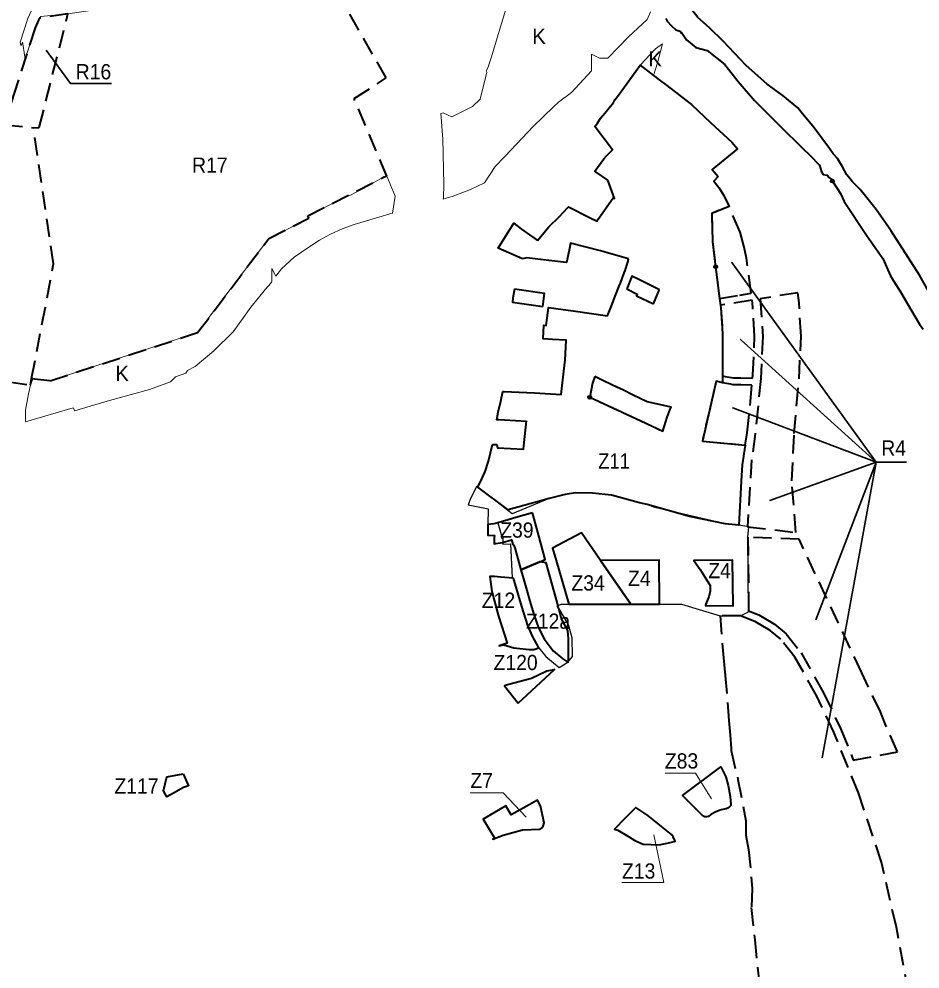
# Model space of a CAD drawing. Extents: x -650276 to -642489, y -1074311 to -1066658.
# Drawn here: x -646603 to -645184, y -1070690 to -1069193 of the extents above; entities that cross this region are included whole.
import ezdxf

# ---------------------------------------------------------------- set-up
doc = ezdxf.new("R2010")
doc.units = 0
doc.header["$LTSCALE"] = 9.6
doc.header["$PDMODE"] = 32
doc.header["$PDSIZE"] = 4.8
doc.linetypes.add('MEDIUM_DASHED', pattern=[4.5, 3, -1.5])
for name, color, linetype, lineweight in [('42', 7, 'Continuous', 25), ('44', 7, 'Continuous', 40), ('45', 7, 'Continuous', 40), ('46', 7, 'Continuous', 13), ('47', 7, 'Continuous', 13), ('48', 7, 'Continuous', 13), ('61', 7, 'MEDIUM_DASHED', 40), ('62', 7, 'Continuous', 35)]:
    doc.layers.add(name, color=color, linetype=linetype, lineweight=lineweight)

msp = doc.modelspace()

# ---------------------------------------------------------------- linework, layer by layer
at = {"layer": '42'}
msp.add_lwpolyline([(-645637.56, -1070114.89), (-645559.63, -1070114.85), (-645499.129, -1070133.293), (-645466.862, -1070133.219), (-645454.051, -1070127.008), (-645455.073, -1070009.111), (-645453.852, -1069992.968), (-645469.701, -1069990.011), (-645490.814, -1069988.074), (-645601.753, -1069962.317), (-645614.072, -1069957.797), (-645625.979, -1069954.92), (-645670.325, -1069943.002), (-645699.889, -1069939.714), (-645726.542, -1069939.398), (-645742.967, -1069941.862), (-645768.424, -1069948.431), (-645826.321, -1069972.247), (-645880.431, -1069930.3), (-645882.381, -1069928.788), (-645892.09, -1069947.98), (-645895.66, -1069958.42), (-645864.48, -1069964.53), (-645864.77, -1069989.26), (-645855.54, -1069988.24), (-645849.1, -1069986.42), (-645842.8, -1070008.59), (-645843.74, -1070010.25), (-645841.43, -1070010.21), (-645841.21, -1070017.31), (-645841.89, -1070017.42), (-645841.075, -1070020.163), (-645828.963, -1070019.709), (-645826.615, -1070073.495), (-645824.28, -1070073.67), (-645811.48, -1070118.65), (-645801.99, -1070148.51), (-645795.07, -1070164.26), (-645784.51, -1070183.77), (-645773.48, -1070197.1), (-645752.54, -1070214.74), (-645739.12, -1070205.9), (-645731.3, -1070197.24), (-645731.94, -1070167.87), (-645737.63, -1070147.39), (-645755.4, -1070117.6), (-645749.28, -1070114.96), (-645737.075, -1070114.955)], close=True, dxfattribs=at)
at = {"layer": '44'}
for points in [[(-645166.67, -1069629), (-645184.88, -1069596.58), (-645202.56, -1069568.23), (-645230.1, -1069525.98), (-645253.4, -1069493.06), (-645278.31, -1069461.33), (-645281.4, -1069458.4), (-645290.5, -1069449.03), (-645299.61, -1069437.97), (-645306.16, -1069425.55), (-645314.14, -1069412.54), (-645321.1, -1069405.21), (-645326.59, -1069396.64), (-645350.63, -1069363.98), (-645371.12, -1069339.47), (-645376.38, -1069332.65), (-645400.07, -1069313.32), (-645424.8, -1069295.24), (-645458.45, -1069265.56), (-645494.13, -1069227.63), (-645515.89, -1069206.66), (-645534.25, -1069190.56), (-645543.43, -1069178.39)], [(-645584.73, -1069191.88), (-645582.63, -1069195.88), (-645575.58, -1069203.57), (-645568.9, -1069209.87), (-645567.07, -1069210.45), (-645562.17, -1069212.02), (-645560.72, -1069214.25), (-645559.33, -1069214.54), (-645552.2, -1069225.59), (-645537.44, -1069237.41), (-645519.59, -1069242.38), (-645491.63, -1069264.25), (-645470.44, -1069291.24), (-645444.62, -1069321.35), (-645405.7, -1069360.27), (-645368.13, -1069397.37), (-645358.04, -1069406.84), (-645342.49, -1069423.06), (-645339.31, -1069433.27), (-645336.66, -1069437.47), (-645330.57, -1069438.89), (-645327.2, -1069442.53), (-645323.36, -1069445.79), (-645322.13, -1069447.96)], [(-645322.13, -1069447.96), (-645309.62, -1069467.79), (-645303.57, -1069480.49), (-645268.57, -1069533.23), (-645242.75, -1069570.26), (-645230.42, -1069597.39), (-645227.27, -1069602.68), (-645225.7, -1069605.32), (-645214.76, -1069622.37), (-645198.41, -1069650.49), (-645185.17, -1069673.38), (-645179.12, -1069681.3)]]:
    msp.add_lwpolyline(points, dxfattribs=at)
at = {"layer": '44', "lineweight": 13}
msp.add_lwpolyline([(-645585.63, -1070380.811), (-645537.799, -1070380.811), (-645512.608, -1070421.471)], dxfattribs=at)
msp.add_lwpolyline([(-645585.63, -1070380.811), (-645537.799, -1070380.811), (-645512.608, -1070421.471)], dxfattribs=at)
at = {"layer": '44'}
msp.add_lwpolyline([(-645497.81, -1070370.93), (-645497.81, -1070370.93), (-645490.19, -1070386.97), (-645486.54, -1070400.38), (-645483.29, -1070417.99), (-645482.62, -1070423.93), (-645481.93, -1070430.04), (-645482.18, -1070432.13), (-645485.67, -1070435.7), (-645489.34, -1070437.05), (-645497.33, -1070438.82), (-645505.88, -1070441.74), (-645513.81, -1070446.24), (-645517.44, -1070449.23), (-645517.95, -1070449.45), (-645520.4, -1070449.87), (-645521.41, -1070449.84), (-645522.95, -1070449.61), (-645524.42, -1070449.16), (-645525.75, -1070448.41), (-645527.34, -1070447.1), (-645558.36, -1070416.1)], close=True, dxfattribs=at)
msp.add_point((-645322.13, -1069447.96), dxfattribs=at)
at = {"layer": '45'}
for p, q in [((-645704.355, -1069788.786), (-645623.75, -1069825.97)), ((-645726.542, -1069939.398), (-645742.967, -1069941.862))]:
    msp.add_line(p, q, dxfattribs=at)
for points in [[(-645668.722, -1069398.75), (-645696.19, -1069362.01), (-645692.38, -1069356.67), (-645690.81, -1069354.28), (-645687.22, -1069349), (-645680.8, -1069341.08), (-645667, -1069324.06), (-645664.89, -1069320.2), (-645658.9, -1069312.83), (-645625.11, -1069265.42), (-645604.114, -1069281.49), (-645594.94, -1069288.511)], [(-645594.94, -1069288.511), (-645583.13, -1069297.55), (-645546.19, -1069325.81), (-645544.26, -1069327.35), (-645513.41, -1069356.18), (-645480.72, -1069386.96), (-645471.738, -1069397.026), (-645511.464, -1069429.794), (-645501.878, -1069440.838)], [(-645675.91, -1069446.56), (-645694.21, -1069433.78), (-645696.45, -1069432.21), (-645682.28, -1069412.88), (-645678.06, -1069408.54), (-645668.61, -1069398.9), (-645668.722, -1069398.75)], [(-645786.388, -1069541.673), (-645779.376, -1069532.962), (-645778.754, -1069532.198), (-645769.369, -1069520.672), (-645768.995, -1069520.305), (-645752.715, -1069504.328), (-645738.986, -1069489.868), (-645737.897, -1069488.534), (-645702.82, -1069506.64), (-645692.87, -1069511.229), (-645690.84, -1069508.32), (-645667.31, -1069474.6), (-645665.58, -1069475.61), (-645675.91, -1069446.56)], [(-645501.878, -1069440.838), (-645508.994, -1069447.955), (-645501, -1069458), (-645493, -1069471), (-645484.783, -1069488.256), (-645512, -1069499), (-645511, -1069544), (-645506, -1069583)], [(-645836.44, -1069534.5), (-645824.05, -1069514.34), (-645811.75, -1069523.81), (-645808.1, -1069526.61), (-645799.07, -1069532.8), (-645790.62, -1069538.59), (-645786.388, -1069541.673)], [(-645810.08, -1069570.39), (-645848.78, -1069553.91), (-645836.44, -1069534.5)], [(-645643.16, -1069570.6), (-645687.29, -1069558.04), (-645734.5, -1069545.89), (-645736.8, -1069556.91), (-645741.14, -1069576.19), (-645769.04, -1069573), (-645803.513, -1069569.263), (-645810.08, -1069570.39)], [(-645676.34, -1069660.28), (-645670.23, -1069644.67), (-645664.19, -1069629.24), (-645657.52, -1069612.2), (-645656.15, -1069608.71), (-645649.91, -1069592.39), (-645648.68, -1069589.06), (-645644.56, -1069575.61), (-645643.16, -1069570.6)], [(-645506, -1069583), (-645500.137, -1069632.833), (-645500.137, -1069632.833)], [(-645594.58, -1069619.56), (-645621.56, -1069605.68), (-645626.95, -1069602.91), (-645638.203, -1069597.8), (-645645.715, -1069618.085)], [(-645823.082, -1069618.279), (-645823.13, -1069618.452), (-645825.295, -1069632.053), (-645826.133, -1069638.843), (-645826.151, -1069639.057), (-645778.45, -1069645.92)], [(-645823.082, -1069618.279), (-645823.13, -1069618.452), (-645825.295, -1069632.053), (-645826.133, -1069638.843), (-645826.151, -1069639.057), (-645778.45, -1069645.92)], [(-645778.45, -1069645.92), (-645775.46, -1069625.13), (-645823.082, -1069618.279)], [(-645778.45, -1069645.92), (-645775.46, -1069625.13), (-645823.082, -1069618.279)], [(-645645.715, -1069618.085), (-645629.78, -1069626.03), (-645630.93, -1069628.84), (-645603.7, -1069641.75)], [(-645603.7, -1069641.75), (-645594.818, -1069620.139), (-645594.58, -1069619.56)], [(-645500.137, -1069632.833), (-645498, -1069648), (-645495, -1069688), (-645495, -1069744), (-645495, -1069766), (-645504.976, -1069763.332), (-645527, -1069858), (-645459.312, -1069864.01), (-645464.288, -1069895.362), (-645465.756, -1069921.035), (-645469.701, -1069990.011)], [(-645839.721, -1069780.247), (-645839.658, -1069779.835), (-645791.2, -1069781.92), (-645749.48, -1069784.61), (-645743.36, -1069733.7), (-645743.01, -1069730.72), (-645741.43, -1069698.68), (-645763.24, -1069697.58), (-645777.62, -1069696.85), (-645776.45, -1069675.26), (-645773.02, -1069675.47), (-645769.36, -1069648), (-645769.264, -1069647.213), (-645726.57, -1069653.22), (-645676.34, -1069660.28)], [(-645696.517, -1069756.039), (-645700.028, -1069766.286), (-645704.355, -1069788.786)], [(-645660.57, -1069773.31), (-645681.76, -1069763.13), (-645696.517, -1069756.039)], [(-645804.185, -1069825.84), (-645804.28, -1069826.76), (-645812.18, -1069826.3), (-645847.62, -1069824.26), (-645850.63, -1069824.09), (-645848.35, -1069812.09), (-645844.57, -1069795.07), (-645841.41, -1069779.76), (-645839.658, -1069779.835), (-645839.721, -1069780.247)], [(-645613.84, -1069795.78), (-645635.79, -1069785.23), (-645652.378, -1069777.251), (-645660.57, -1069773.31)], [(-645623.75, -1069825.97), (-645589.23, -1069841.89), (-645582.31, -1069820.05), (-645577.52, -1069807.26), (-645576.34, -1069804.13), (-645578.134, -1069803.731), (-645613.84, -1069795.78)], [(-645742.967, -1069941.862), (-645768.424, -1069948.431), (-645833, -1069966), (-645880.431, -1069930.3), (-645874.219, -1069917.496), (-645869.262, -1069905.935), (-645863.95, -1069889.468), (-645857.289, -1069863.338), (-645857.204, -1069862.954), (-645850.92, -1069863.41), (-645849.79, -1069868.4), (-645808.84, -1069870.75), (-645808.28, -1069865.39), (-645804.185, -1069825.84)], [(-645469.701, -1069990.011), (-645490.814, -1069988.074), (-645547.4, -1069976.382), (-645614.072, -1069957.797), (-645625.979, -1069954.92), (-645670.325, -1069943.002), (-645699.889, -1069939.714), (-645726.542, -1069939.398)], [(-645794.679, -1069970.596), (-645821, -1069978), (-645833, -1069982)], [(-645794.679, -1069970.596), (-645821, -1069978), (-645833, -1069982)], [(-645777.143, -1070034.287), (-645786.238, -1070001.251), (-645794.679, -1069970.596)], [(-645777.143, -1070034.287), (-645786.238, -1070001.251), (-645794.679, -1069970.596)], [(-645833, -1069982), (-645849.1, -1069986.42), (-645855.54, -1069988.24), (-645864.77, -1069989.26), (-645864.97, -1070006.16), (-645854.42, -1070006.47), (-645854.65, -1070010.44), (-645855.17, -1070019.44), (-645852.36, -1070019.01), (-645852.33, -1070019.2), (-645845.37, -1070018.12), (-645845.14, -1070018.08), (-645845.17, -1070017.91), (-645841.89, -1070017.42), (-645827.365, -1070013.291), (-645825.08, -1070021.52)], [(-645833, -1069982), (-645849.1, -1069986.42), (-645855.54, -1069988.24), (-645864.77, -1069989.26), (-645864.97, -1070006.16), (-645854.42, -1070006.47), (-645854.65, -1070010.44), (-645855.17, -1070019.44), (-645852.36, -1070019.01), (-645852.33, -1070019.2), (-645845.37, -1070018.12), (-645845.14, -1070018.08), (-645845.17, -1070017.91), (-645841.89, -1070017.42), (-645827.365, -1070013.291), (-645825.08, -1070021.52)], [(-645825.08, -1070021.52), (-645823.76, -1070021.67), (-645822.549, -1070025.948), (-645812.76, -1070060.53), (-645783.063, -1070047.855), (-645774.423, -1070044.167), (-645777.143, -1070034.287)], [(-645825.08, -1070021.52), (-645823.76, -1070021.67), (-645822.549, -1070025.948), (-645812.76, -1070060.53), (-645783.063, -1070047.855), (-645774.423, -1070044.167), (-645777.143, -1070034.287)], [(-645753.182, -1070121.317), (-645755.4, -1070117.6), (-645754.333, -1070117.14), (-645772.853, -1070049.868), (-645783.063, -1070047.855), (-645812.76, -1070060.53), (-645808.721, -1070074.795), (-645804.52, -1070089.63), (-645797.66, -1070113.88), (-645791.72, -1070132.59)], [(-645824.28, -1070073.67), (-645845.01, -1070072.12), (-645854.25, -1070071.4), (-645861.74, -1070070.95), (-645858.53, -1070094.64), (-645847.88, -1070133.4)], [(-645795.07, -1070164.26), (-645801.99, -1070148.51), (-645811.48, -1070118.65), (-645824.28, -1070073.67)], [(-645737.756, -1070204.389), (-645737.624, -1070169.544), (-645738.79, -1070156.281), (-645748.62, -1070137.889), (-645753.182, -1070121.317)], [(-645847.88, -1070133.4), (-645834.31, -1070176.15), (-645847.2, -1070180.14), (-645839.82, -1070178.94), (-645824.12, -1070183.63), (-645799.91, -1070186.32), (-645792.37, -1070186.01), (-645784.51, -1070183.77), (-645795.07, -1070164.26)], [(-645791.72, -1070132.59), (-645784.83, -1070151.9), (-645776.26, -1070169.44), (-645771.246, -1070175.64)], [(-645771.246, -1070175.64), (-645761.78, -1070188.29), (-645746.73, -1070201.04), (-645739.12, -1070205.9), (-645737.756, -1070204.389)]]:
    msp.add_lwpolyline(points, dxfattribs=at)
for points in [[(-645639.638, -1070114.895), (-645687.31, -1070045.724), (-645717.36, -1070002.12), (-645762.868, -1070026.606), (-645757.215, -1070045.97), (-645737.075, -1070114.955)], [(-645639.638, -1070114.895), (-645687.31, -1070045.724), (-645717.36, -1070002.12), (-645762.868, -1070026.606), (-645757.215, -1070045.97), (-645737.075, -1070114.955)], [(-645639.638, -1070114.895), (-645594.733, -1070114.868), (-645595.2, -1070045.403), (-645687.31, -1070045.724)], [(-645639.638, -1070114.895), (-645594.733, -1070114.868), (-645595.2, -1070045.403), (-645687.31, -1070045.724)], [(-645522.587, -1070116.952), (-645478.664, -1070117.114), (-645479.429, -1070045.409), (-645540.433, -1070045.752), (-645530.3, -1070060.08), (-645514.49, -1070085.4), (-645514.56, -1070090.91), (-645514.61, -1070094.35), (-645517.02, -1070103.08), (-645518.35, -1070106.87), (-645521.73, -1070114.83)], [(-645522.587, -1070116.952), (-645478.664, -1070117.114), (-645479.429, -1070045.409), (-645540.433, -1070045.752), (-645530.3, -1070060.08), (-645514.49, -1070085.4), (-645514.56, -1070090.91), (-645514.61, -1070094.35), (-645517.02, -1070103.08), (-645518.35, -1070106.87), (-645521.73, -1070114.83)], [(-645816.9, -1070270.96), (-645760.05, -1070217.79), (-645760.91, -1070217.98), (-645772.08, -1070220.39), (-645795.85, -1070231.81), (-645833.92, -1070241.96), (-645838.53, -1070243.19)], [(-646344.93, -1070382.33), (-646336.25, -1070400.875), (-646344.26, -1070403.84), (-646359.769, -1070412.361), (-646370.56, -1070418.29), (-646375.63, -1070408.76), (-646370.624, -1070386.792)], [(-645862.66, -1070469.5), (-645853.98, -1070483.81), (-645856.87, -1070485.24), (-645840.59, -1070479), (-645810.44, -1070470.17), (-645782.57, -1070469.22), (-645780.38, -1070467.64), (-645777.8, -1070464.4), (-645776.04, -1070459.38), (-645782.13, -1070432.59), (-645786.9, -1070423.81), (-645804.58, -1070433.53), (-645828.24, -1070446.54), (-645836.32, -1070432.55), (-645872.35, -1070453.55)], [(-645862.66, -1070469.5), (-645853.98, -1070483.81), (-645856.87, -1070485.24), (-645840.59, -1070479), (-645810.44, -1070470.17), (-645782.57, -1070469.22), (-645780.38, -1070467.64), (-645777.8, -1070464.4), (-645776.04, -1070459.38), (-645782.13, -1070432.59), (-645786.9, -1070423.81), (-645804.58, -1070433.53), (-645828.24, -1070446.54), (-645836.32, -1070432.55), (-645872.35, -1070453.55)], [(-645594.769, -1070494.065), (-645577.47, -1070490.3), (-645571.13, -1070488.89), (-645569.97, -1070488.3), (-645572.86, -1070481.41), (-645575.7, -1070477.77), (-645591.49, -1070465.19), (-645594.62, -1070462.7), (-645612.77, -1070447.82), (-645631.63, -1070435.3), (-645636.42, -1070439.93), (-645648.9, -1070452.38), (-645665.6, -1070469.04), (-645660.29, -1070471.12), (-645643.4, -1070481.02), (-645633.35, -1070486.91), (-645620.22, -1070493)], [(-645594.769, -1070494.065), (-645577.47, -1070490.3), (-645571.13, -1070488.89), (-645569.97, -1070488.3), (-645572.86, -1070481.41), (-645575.7, -1070477.77), (-645591.49, -1070465.19), (-645594.62, -1070462.7), (-645612.77, -1070447.82), (-645631.63, -1070435.3), (-645636.42, -1070439.93), (-645648.9, -1070452.38), (-645665.6, -1070469.04), (-645660.29, -1070471.12), (-645643.4, -1070481.02), (-645633.35, -1070486.91), (-645620.22, -1070493)]]:
    msp.add_lwpolyline(points, close=True, dxfattribs=at)
for p in [(-645506, -1069583), (-645704.355, -1069788.786)]:
    msp.add_point(p, dxfattribs=at)
at = {"layer": '46'}
for points in [[(-645892.796, -1070412.223), (-645840.481, -1070412.223), (-645804.515, -1070450.215)], [(-645892.796, -1070412.223), (-645840.481, -1070412.223), (-645804.515, -1070450.215)], [(-645653.64, -1070553.576), (-645587.872, -1070553.576), (-645603.567, -1070478.038)], [(-645653.64, -1070553.576), (-645587.872, -1070553.576), (-645603.567, -1070478.038)]]:
    msp.add_lwpolyline(points, dxfattribs=at)
at = {"layer": '47'}
for points in [[(-646593.793, -1069255.911), (-646577.878, -1069206.485), (-646572.586, -1069194.485), (-646569.114, -1069188.86), (-646526.31, -1069184.381), (-646479.84, -1069177.626), (-646250.409, -1069137.52), (-646153.307, -1069059.947), (-646161.484, -1069046.228), (-646256.824, -1069123.414)], [(-646547.412, -1069071.71), (-646549.91, -1069072.542), (-646564.54, -1069125.08), (-646564.605, -1069125.271), (-646574.978, -1069163.017), (-646574.978, -1069163.017), (-646574.33, -1069162.04), (-646575.87, -1069164.54), (-646581.29, -1069173.32), (-646589.56, -1069192.07), (-646601.41, -1069229.34)], [(-645835.157, -1069172.184), (-645859.43, -1069254.08), (-645864.96, -1069269.78), (-645867.42, -1069274.21), (-645866.45, -1069276.32), (-645877.15, -1069319.06), (-645877.15, -1069319.06), (-645889.29, -1069330.52), (-645921.56, -1069346.6), (-645935.33, -1069340.64), (-645938.89, -1069341.56), (-645938.399, -1069347.452)], [(-645938.399, -1069347.452), (-645936.046, -1069375.651), (-645935.58, -1069381.24), (-645933.97, -1069453.52), (-645934.8, -1069474.71), (-645935.05, -1069476.32), (-645928.99, -1069474.55), (-645921.13, -1069472.25), (-645892.03, -1069461.43), (-645869.91, -1069451.02), (-645853.28, -1069425.27), (-645838.17, -1069409.28), (-645819.62, -1069389.66), (-645793.63, -1069362.15), (-645761.411, -1069331.17), (-645753.58, -1069323.64), (-645733.1, -1069308.58), (-645701.62, -1069274.36), (-645701.33, -1069247.86), (-645689, -1069254.5), (-645675.82, -1069254.48), (-645643.34, -1069220.59), (-645613.9, -1069193.45), (-645608.71, -1069181.51)], [(-646601.41, -1069229.34), (-646600.68, -1069234.21), (-646599.79, -1069234.07), (-646597.77, -1069229.37), (-646596.95, -1069234.83), (-646593.793, -1069255.911)], [(-645604.114, -1069281.49), (-645597.738, -1069261.522), (-645589.844, -1069231.908), (-645600.55, -1069239.93), (-645625.11, -1069265.42)], [(-645625.11, -1069265.42), (-645625.11, -1069265.42), (-645604.114, -1069281.49)], [(-646023.96, -1069440.34), (-646028.16, -1069441.58), (-646080.35, -1069469.89), (-646102.15, -1069479.49), (-646148.5, -1069503), (-646146.8, -1069506.6), (-646189.17, -1069528.74), (-646209.9, -1069538.5), (-646321.973, -1069686.855), (-646554.262, -1069762.602), (-646581.489, -1069759.421), (-646585.51, -1069769.57)], [(-646017.63, -1069499.08), (-646017.63, -1069499.08), (-646015.16, -1069498.74), (-646010.65, -1069471.91), (-646023.96, -1069440.34)], [(-646491.18, -1069802.78), (-646491.18, -1069802.78), (-646460.97, -1069793.56), (-646397.74, -1069776.29), (-646364.67, -1069764.23), (-646357, -1069756.7), (-646340.48, -1069750.92), (-646337.97, -1069746.4), (-646325.92, -1069740.05), (-646296.64, -1069715.72), (-646266.27, -1069685.75), (-646250, -1069663.09), (-646238.19, -1069646.63), (-646212.43, -1069615.33), (-646210.03, -1069612.42), (-646205.9, -1069607.17), (-646205, -1069606.03), (-646205.25, -1069585.67), (-646198.82, -1069597.83), (-646190.07, -1069586.48), (-646169.9, -1069568.04), (-646146.81, -1069551.97), (-646129.87, -1069541.19), (-646112.56, -1069531.78), (-646094.39, -1069523.34), (-646075.48, -1069516.38), (-646020.75, -1069500), (-646017.63, -1069499.08)], [(-646585.51, -1069769.57), (-646588.25, -1069783.37), (-646593.34, -1069808.99), (-646593.34, -1069827.68)], [(-646593.34, -1069827.68), (-646518.19, -1069805.27), (-646515.63, -1069810.24), (-646491.18, -1069802.78)]]:
    msp.add_lwpolyline(points, dxfattribs=at)
at = {"layer": '61'}
for points in [[(-646583.457, -1069759.191), (-646554.262, -1069762.602), (-646321.973, -1069686.855), (-646209.9, -1069538.5), (-646146.8, -1069506.6), (-646148.5, -1069503), (-646028.16, -1069441.58), (-646023.96, -1069440.34), (-646075.49, -1069318.19), (-646025.14, -1069285.394), (-646153.307, -1069059.947)], [(-646642.89, -1069357.68), (-646652.72, -1069388.08), (-646677.18, -1069463.79), (-646693.58, -1069550.28), (-646698.4, -1069578.93), (-646697.31, -1069579.97), (-646697.31, -1069583.47), (-646666.36, -1069588.57), (-646659.83, -1069601.8), (-646659.52, -1069605.53), (-646662.57, -1069621.66), (-646671.69, -1069669.92), (-646678.52, -1069705.63), (-646680.28, -1069714.83), (-646677.36, -1069733.65), (-646679.46, -1069745.37), (-646622, -1069759.34), (-646619.49, -1069764.46), (-646585.51, -1069769.57), (-646583.457, -1069759.191), (-646548.91, -1069578.56), (-646580.797, -1069364.111)], [(-645202.41, -1070726.571), (-645221.272, -1070623.729), (-645244.808, -1070521.357), (-645281.252, -1070412.013), (-645319.69, -1070316.63), (-645346.844, -1070259.875), (-645381.213, -1070198.011), (-645403.604, -1070169.942), (-645420.081, -1070156.179), (-645443.191, -1070142.473), (-645454.881, -1070137.836), (-645466.862, -1070133.22), (-645499.142, -1070133.293), (-645493.76, -1070199.15), (-645490.95, -1070226.89), (-645485.21, -1070298.03), (-645483.34, -1070321.17), (-645481.65, -1070342.07), (-645481.67, -1070345.39), (-645471, -1070391), (-645458.32, -1070455.91), (-645458.46, -1070478.86), (-645454.02, -1070501.52), (-645448.36, -1070563), (-645449.82, -1070592.72), (-645444.47, -1070643.85), (-645435.711, -1070727.497)]]:
    msp.add_lwpolyline(points, dxfattribs=at)
for points in [[(-646572.586, -1069194.485), (-646577.878, -1069206.485), (-646611.107, -1069309.68), (-646626.774, -1069359.349), (-646580.797, -1069364.111), (-646571.479, -1069363.822), (-646526.31, -1069184.381), (-646570.296, -1069190.776)], [(-645506, -1069583), (-645500.137, -1069632.833), (-645468, -1069627.622), (-645450.05, -1069624.711), (-645457.223, -1069569.632), (-645461.32, -1069552.039), (-645467.477, -1069528.79), (-645484.783, -1069488.256), (-645512, -1069499), (-645511, -1069544)], [(-645374.642, -1069640.059), (-645376.605, -1069623.944), (-645435.877, -1069633.555), (-645431.642, -1069692.811), (-645434.826, -1069759.235), (-645443.679, -1069846.142), (-645449.445, -1069887.328), (-645455.84, -1069992.731), (-645379.881, -1070001.766), (-645385.95, -1069920.347), (-645382.14, -1069845.883), (-645378.587, -1069802.788), (-645374.542, -1069758.923), (-645371.563, -1069692.39)], [(-645495, -1069688), (-645495, -1069744), (-645495, -1069754.815), (-645491, -1069756), (-645478, -1069758), (-645466.517, -1069758.328), (-645447.852, -1069758.862), (-645447.398, -1069753.935), (-645444.664, -1069692.902), (-645447.387, -1069646.623), (-645448.725, -1069635.639), (-645498.61, -1069643.729), (-645498, -1069648)], [(-645504.976, -1069763.332), (-645527, -1069858), (-645464.93, -1069863.477), (-645459.312, -1069864.01), (-645456.586, -1069844.534), (-645451.227, -1069795.473), (-645448.864, -1069769.837), (-645466.353, -1069769.337), (-645478.997, -1069768.976), (-645482.753, -1069768.26), (-645495, -1069766)], [(-645374.685, -1070012.289), (-645455.073, -1070009.111), (-645454.066, -1070125.249), (-645437.885, -1070131.669), (-645413.129, -1070146.351), (-645394.98, -1070161.51), (-645371.209, -1070191.309), (-645336.176, -1070254.367), (-645308.702, -1070311.792), (-645289.153, -1070360.302), (-645219.594, -1070347.682), (-645238.856, -1070303.185), (-645246.433, -1070284.382), (-645275.729, -1070223.153)]]:
    msp.add_lwpolyline(points, close=True, dxfattribs=at)
at = {"layer": '62'}
msp.add_line((-645253.165, -1069890.903), (-645338.143, -1070356.741), dxfattribs=at)
for points in [[(-646457.55, -1069294.294), (-646522.377, -1069294.294), (-646560.609, -1069241.94)], [(-645205.454, -1069890.903), (-645253.165, -1069890.903), (-645480.406, -1069576.285), (-645253.165, -1069890.903), (-645466.774, -1069697.69), (-645253.165, -1069890.903), (-645479.043, -1069805.455), (-645253.165, -1069890.903), (-645420.426, -1069951.415), (-645253.165, -1069890.903), (-645348.178, -1070139.662)]]:
    msp.add_lwpolyline(points, dxfattribs=at)
at = {"layer": '62', "lineweight": 13}
msp.add_lwpolyline([(-646457.55, -1069294.294), (-646522.377, -1069294.294), (-646560.609, -1069241.94)], dxfattribs=at)

# ---------------------------------------------------------------- texts
at = {"layer": '44', "width": 0.95}
msp.add_text('Z83', height=24, dxfattribs=at).set_placement((-645586.057, -1070373.732))
msp.add_text('Z83', height=24, dxfattribs=at).set_placement((-645586.057, -1070373.732))
at = {"layer": '45', "width": 0.9}
msp.add_text('Z11', height=24, dxfattribs=at).set_placement((-645690.933, -1069901.172))
at = {"layer": '46', "width": 0.95}
for s, p in [('Z39', (-645845.387, -1070009.975)), ('Z39', (-645845.387, -1070009.975)), ('Z4', (-645517.623, -1070073.78)), ('Z4', (-645517.623, -1070073.78)), ('Z34', (-645733.26, -1070093.266)), ('Z34', (-645733.26, -1070093.266)), ('Z4', (-645644.02, -1070085.964)), ('Z4', (-645644.02, -1070085.964)), ('Z12', (-645874.409, -1070120.563)), ('Z12a', (-645804.738, -1070153.542)), ('Z120', (-645855.898, -1070218.668)), ('Z7', (-645892.427, -1070404.622)), ('Z7', (-645892.427, -1070404.622)), ('Z117', (-646453.122, -1070413.348)), ('Z13', (-645653.625, -1070547.221)), ('Z13', (-645653.625, -1070547.221))]:
    msp.add_text(s, height=24, dxfattribs=at).set_placement(p)
at = {"layer": '48'}
for p in [(-645795.003, -1069231.861), (-645795.003, -1069231.861), (-645611.977, -1069267.447), (-646451.743, -1069763.13), (-646451.743, -1069763.13)]:
    msp.add_text('K', height=24, dxfattribs=at).set_placement(p)
at = {"layer": '62', "width": 0.95}
for s, p in [('R16', (-646514.063, -1069287.733)), ('R17', (-646330.736, -1069434.917)), ('R4', (-645245.139, -1069880.683))]:
    msp.add_text(s, height=24, dxfattribs=at).set_placement(p)

doc.saveas('drawing.dxf')
